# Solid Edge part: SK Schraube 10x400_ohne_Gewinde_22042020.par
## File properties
Author: fknapp
Template: Normal.par
Last saved by: fknapp
Revision: 32
Application: Solid Edge
Username: fknapp
Material: Aluminium
Genauigkeit: 0,99
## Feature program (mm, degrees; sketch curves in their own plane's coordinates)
sketch for "unnamed RevolvedProtrusion 1" plane through (0, 0, 0) normal (0, 0, 1) x-axis (1, 0, 0)
  line (0, 54) -> (9, 54)
  line (9, 54) -> (9, 53)
  line (9, 53) -> (5, 49)
  line (5, 49) -> (5, 46.3)
  line (5, 46.3) -> (4.7548, 46.3)
  arc centre (4.7548, 44.6952) radius 1.6048 from (4.7548, 46.3) to (3.15, 44.6952) ccw
  line (3.15, 44.6952) -> (3.15, 42)
  line (3.15, 42) -> (5, 42)
  line (5, -333) -> (5, 42)
  line (0.5, -346) -> (5, -333)
  line (0, -346) -> (0.5, -346)
revolve "unnamed RevolvedProtrusion 1" add full turn 360 deg about sketch line (0, 54) -> (0, -346)
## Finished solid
Body 1: solid body, 11 faces, 10 edges, 0 vertices.
  Faces by surface: cylinder 4, plane 4, cone 2, torus 1
  Edges by curve: circle 10
Bounding box of the edges (mm; curved faces can reach further): 18.000 x 400.000 x 18.000, from (-9, -346, -9) to (9, 54, 9).
Cylindrical faces by radius (mm): R3.15 x1, R5 x2, R9 x1
Conical faces (half-angle, radius in mm at the cone's reference point): 19.0935 deg R5 x1, 45 deg R9 x1
Toroidal faces (ring radius, tube radius in mm): R4.7548 r1.6048 x1
Planar faces by outward normal: +y 2, -y 2
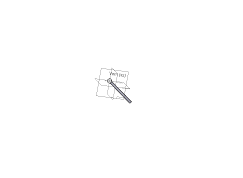
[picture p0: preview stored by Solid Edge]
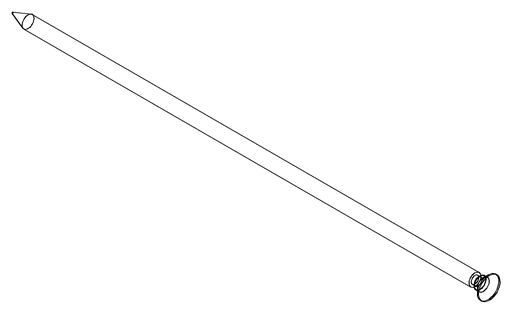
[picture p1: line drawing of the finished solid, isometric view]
